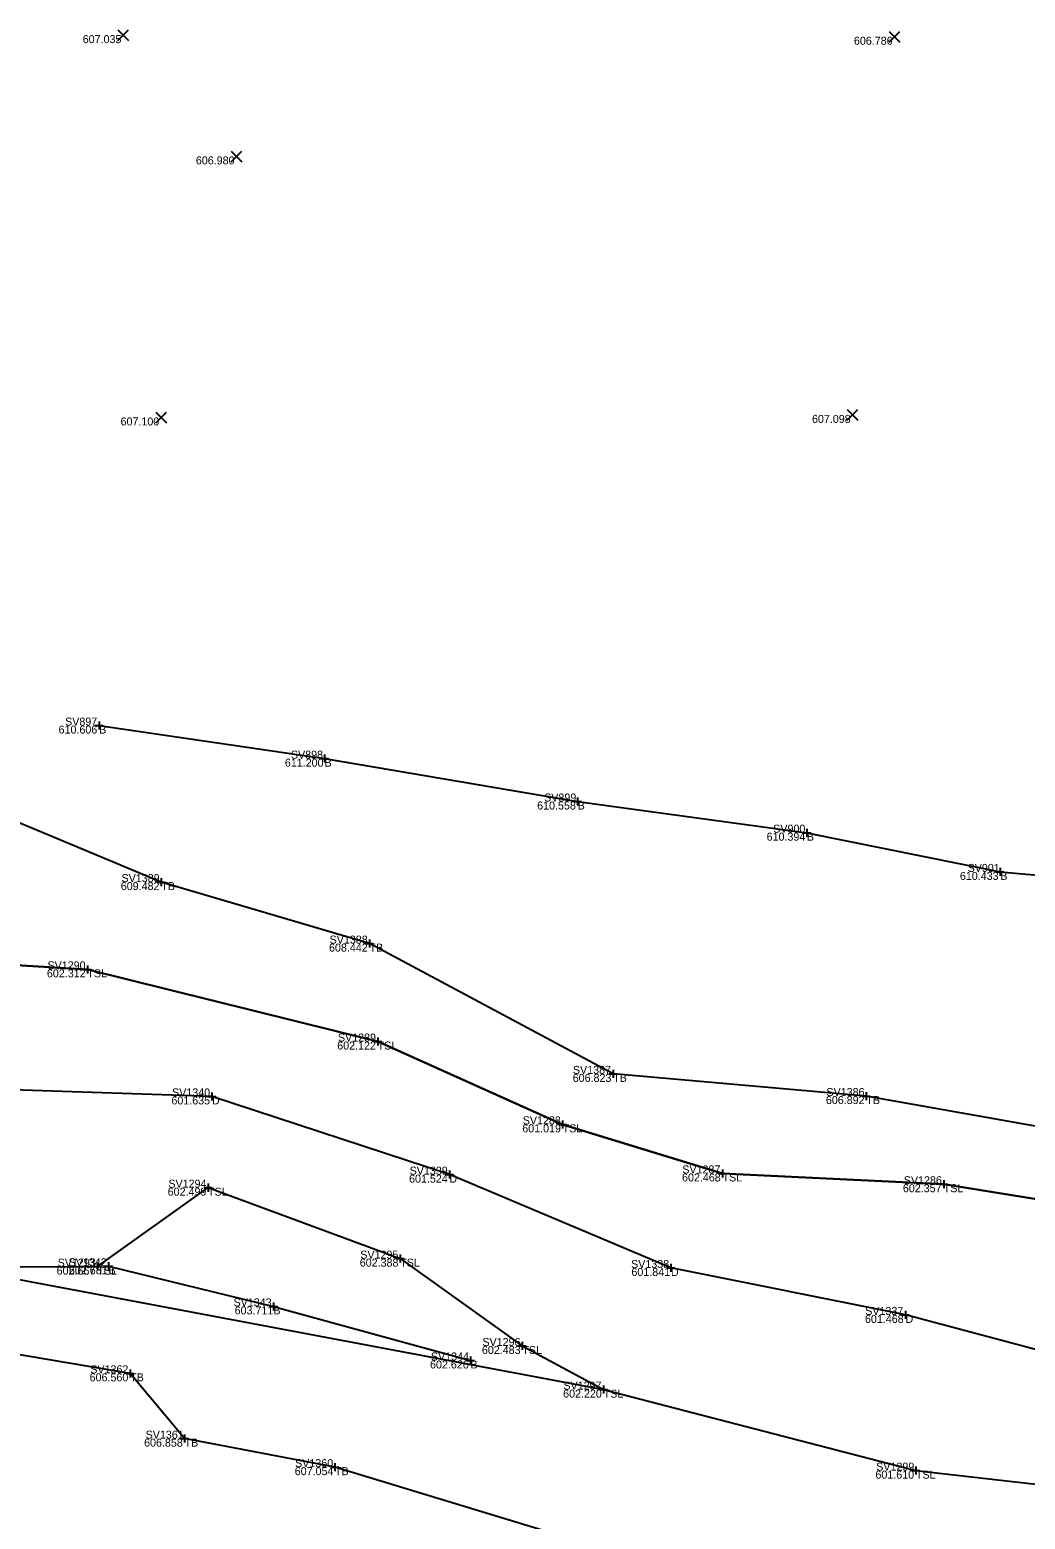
# Model space of a CAD drawing. Extents: x -2 to 1979875, y -2 to 232027.
# Drawn here: x 1978636.7 to 1978698.9, y 231261.4 to 231354.5 of the extents above; entities that cross this region are included whole.
import ezdxf

# ---------------------------------------------------------------- set-up
doc = ezdxf.new("R2010")
doc.units = 0
for name, color, linetype in [('_CIVIL_CONSTRUCTION', 7, 'Continuous'), ('DR_X_Ditch', 7, 'Continuous'), ('GE_P_Alignment', 7, 'Continuous'), ('GE_X_Alignment', 7, 'Continuous'), ('GE_X_Alignment_100_Curve_Data', 7, 'Continuous'), ('GE_X_Alignment_100_Stations', 7, 'Continuous'), ('HY_X_Water_Edge', 7, 'Continuous'), ('SV_X_Random_Point', 7, 'Continuous'), ('SV_X_Toe_of_Slope', 7, 'Continuous'), ('SV_X_Top_of_Bank', 7, 'Continuous')]:
    doc.layers.add(name, color=color, linetype=linetype)

msp = doc.modelspace()

# ---------------------------------------------------------------- linework, layer by layer
at = {"layer": 'DR_X_Ditch'}
msp.add_lwpolyline([(1978761.843, 231269.601), (1978754.066, 231268.151), (1978735.568, 231267.758), (1978719.025, 231269.165), (1978704.244, 231270.76), (1978691.436, 231274.176), (1978676.783, 231277.108), (1978662.935, 231282.94), (1978648.103, 231287.828), (1978629.385, 231288.446)], dxfattribs=at)
at = {"layer": 'GE_P_Alignment'}
for points in [[(1978641.051, 231310.998), (1978655.138, 231308.931), (1978670.953, 231306.253), (1978685.276, 231304.307), (1978697.362, 231301.855), (1978713.221, 231300.454), (1978725.92, 231300.85), (1978736.644, 231301.3), (1978747.238, 231303.286)], [(1978641.635, 231277.218), (1978651.938, 231274.71), (1978664.261, 231271.33)]]:
    msp.add_lwpolyline(points, dxfattribs=at)
at = {"layer": 'GE_X_Alignment_100_Curve_Data'}
for p, q in [((1978641.051, 231311.248), (1978641.051, 231310.748)), ((1978640.801, 231310.998), (1978641.301, 231310.998)), ((1978641.051, 231310.998), (1978641.051, 231310.998)), ((1978655.138, 231309.181), (1978655.138, 231308.681)), ((1978654.888, 231308.931), (1978655.388, 231308.931)), ((1978655.138, 231308.931), (1978655.138, 231308.931)), ((1978670.953, 231306.503), (1978670.953, 231306.003)), ((1978670.703, 231306.253), (1978671.203, 231306.253)), ((1978670.953, 231306.253), (1978670.953, 231306.253)), ((1978685.276, 231304.557), (1978685.276, 231304.057)), ((1978685.026, 231304.307), (1978685.526, 231304.307)), ((1978685.276, 231304.307), (1978685.276, 231304.307)), ((1978697.112, 231301.855), (1978697.612, 231301.855)), ((1978697.362, 231302.105), (1978697.362, 231301.605)), ((1978697.362, 231301.855), (1978697.362, 231301.855)), ((1978644.684, 231301.22), (1978645.184, 231301.22)), ((1978644.934, 231301.47), (1978644.934, 231300.97)), ((1978644.934, 231301.22), (1978644.934, 231301.22)), ((1978657.695, 231297.376), (1978658.195, 231297.376)), ((1978657.945, 231297.626), (1978657.945, 231297.126)), ((1978657.945, 231297.376), (1978657.945, 231297.376)), ((1978640.068, 231295.767), (1978640.568, 231295.767)), ((1978640.318, 231296.017), (1978640.318, 231295.517)), ((1978640.318, 231295.767), (1978640.318, 231295.767)), ((1978658.457, 231291.507), (1978658.457, 231291.007)), ((1978658.207, 231291.257), (1978658.707, 231291.257)), ((1978658.457, 231291.257), (1978658.457, 231291.257)), ((1978672.919, 231289.236), (1978673.419, 231289.236)), ((1978673.169, 231289.486), (1978673.169, 231288.986)), ((1978673.169, 231289.236), (1978673.169, 231289.236)), ((1978647.853, 231287.828), (1978648.353, 231287.828)), ((1978648.103, 231288.078), (1978648.103, 231287.578)), ((1978648.103, 231287.828), (1978648.103, 231287.828)), ((1978688.741, 231287.85), (1978689.241, 231287.85)), ((1978688.991, 231288.1), (1978688.991, 231287.6)), ((1978688.991, 231287.85), (1978688.991, 231287.85)), ((1978669.763, 231286.083), (1978670.263, 231286.083)), ((1978670.013, 231286.333), (1978670.013, 231285.833)), ((1978670.013, 231286.083), (1978670.013, 231286.083)), ((1978662.935, 231283.19), (1978662.935, 231282.69)), ((1978680.005, 231283.266), (1978680.005, 231282.766)), ((1978647.857, 231282.377), (1978647.857, 231281.877)), ((1978662.685, 231282.94), (1978663.185, 231282.94)), ((1978662.935, 231282.94), (1978662.935, 231282.94)), ((1978679.755, 231283.016), (1978680.255, 231283.016)), ((1978680.005, 231283.016), (1978680.005, 231283.016)), ((1978693.576, 231282.342), (1978694.076, 231282.342)), ((1978693.826, 231282.592), (1978693.826, 231282.092)), ((1978693.826, 231282.342), (1978693.826, 231282.342)), ((1978647.607, 231282.127), (1978648.107, 231282.127)), ((1978647.857, 231282.127), (1978647.857, 231282.127)), ((1978659.618, 231277.693), (1978660.118, 231277.693)), ((1978659.868, 231277.943), (1978659.868, 231277.443)), ((1978659.868, 231277.693), (1978659.868, 231277.693)), ((1978640.697, 231277.193), (1978641.197, 231277.193)), ((1978640.947, 231277.443), (1978640.947, 231276.943)), ((1978640.947, 231277.193), (1978640.947, 231277.193)), ((1978641.385, 231277.218), (1978641.885, 231277.218)), ((1978641.635, 231277.468), (1978641.635, 231276.968)), ((1978641.635, 231277.218), (1978641.635, 231277.218)), ((1978676.533, 231277.108), (1978677.033, 231277.108)), ((1978676.783, 231277.358), (1978676.783, 231276.858)), ((1978676.783, 231277.108), (1978676.783, 231277.108)), ((1978651.938, 231274.96), (1978651.938, 231274.46)), ((1978651.688, 231274.71), (1978652.188, 231274.71)), ((1978651.938, 231274.71), (1978651.938, 231274.71)), ((1978691.186, 231274.176), (1978691.686, 231274.176)), ((1978691.436, 231274.426), (1978691.436, 231273.926)), ((1978691.436, 231274.176), (1978691.436, 231274.176)), ((1978667.245, 231272.236), (1978667.745, 231272.236)), ((1978667.495, 231272.486), (1978667.495, 231271.986)), ((1978667.495, 231272.236), (1978667.495, 231272.236)), ((1978664.011, 231271.33), (1978664.511, 231271.33)), ((1978664.261, 231271.58), (1978664.261, 231271.08)), ((1978664.261, 231271.33), (1978664.261, 231271.33)), ((1978642.74, 231270.526), (1978643.24, 231270.526)), ((1978642.99, 231270.776), (1978642.99, 231270.276)), ((1978642.99, 231270.526), (1978642.99, 231270.526)), ((1978672.326, 231269.509), (1978672.826, 231269.509)), ((1978672.576, 231269.759), (1978672.576, 231269.259)), ((1978672.576, 231269.509), (1978672.576, 231269.509)), ((1978646.141, 231266.446), (1978646.641, 231266.446)), ((1978646.391, 231266.696), (1978646.391, 231266.196)), ((1978646.391, 231266.446), (1978646.391, 231266.446)), ((1978655.54, 231264.664), (1978656.04, 231264.664)), ((1978655.79, 231264.914), (1978655.79, 231264.414)), ((1978655.79, 231264.664), (1978655.79, 231264.664)), ((1978692.09, 231264.697), (1978692.09, 231264.197)), ((1978691.84, 231264.447), (1978692.34, 231264.447)), ((1978692.09, 231264.447), (1978692.09, 231264.447))]:
    msp.add_line(p, q, dxfattribs=at)
at = {"layer": 'HY_X_Water_Edge'}
for points in [[(1978627.995, 231296.512), (1978640.318, 231295.767), (1978658.457, 231291.257), (1978670.013, 231286.083), (1978680.005, 231283.016), (1978693.826, 231282.342), (1978711.084, 231279.554), (1978722.197, 231278.71), (1978738.528, 231278.008), (1978757.257, 231280.755)], [(1978631.824, 231277.19), (1978672.576, 231269.509), (1978692.09, 231264.447), (1978710.396, 231262.363), (1978725.371, 231260.246)]]:
    msp.add_lwpolyline(points, dxfattribs=at)
at = {"layer": 'SV_X_Random_Point'}
for p, q in [((1978642.228, 231353.803), (1978642.894, 231354.471)), ((1978642.228, 231354.471), (1978642.894, 231353.803)), ((1978690.415, 231353.702), (1978691.081, 231354.37)), ((1978690.415, 231354.37), (1978691.081, 231353.702)), ((1978649.294, 231346.226), (1978649.96, 231346.894)), ((1978649.294, 231346.894), (1978649.96, 231346.226)), ((1978644.59, 231329.916), (1978645.256, 231330.584)), ((1978644.59, 231330.584), (1978645.256, 231329.916)), ((1978687.793, 231330.075), (1978688.459, 231330.743)), ((1978687.793, 231330.743), (1978688.459, 231330.075))]:
    msp.add_line(p, q, dxfattribs=at)
at = {"layer": 'SV_X_Toe_of_Slope'}
for points in [[(1978763.371, 231281.556), (1978757.257, 231280.755), (1978753.761, 231278.898), (1978748.177, 231275.596), (1978738.528, 231278.008), (1978722.197, 231278.71), (1978711.084, 231279.554), (1978693.826, 231282.342), (1978680.005, 231283.016), (1978670.013, 231286.083), (1978658.457, 231291.257), (1978640.318, 231295.767), (1978627.995, 231296.512)], [(1978631.824, 231277.19), (1978640.947, 231277.193), (1978647.857, 231282.127), (1978659.868, 231277.693), (1978667.495, 231272.236), (1978672.576, 231269.509), (1978692.09, 231264.447), (1978710.396, 231262.363), (1978725.371, 231260.246), (1978739.363, 231256.715), (1978742.039, 231254.081), (1978741.875, 231245.466), (1978742.317, 231240.483), (1978743.738, 231236.887), (1978745.947, 231227.451)]]:
    msp.add_lwpolyline(points, dxfattribs=at)
at = {"layer": 'SV_X_Top_of_Bank'}
for points in [[(1978723.688, 231283.348), (1978710.826, 231283.978), (1978688.991, 231287.85), (1978673.169, 231289.236), (1978657.945, 231297.376), (1978644.934, 231301.22), (1978630.359, 231307.302)], [(1978743.6, 231227.215), (1978742.461, 231237.956), (1978739.46, 231251.574), (1978732.39, 231256.429), (1978722.837, 231257.109), (1978701.711, 231257.875), (1978681.567, 231257.575), (1978668.738, 231260.724), (1978655.79, 231264.664), (1978646.391, 231266.446), (1978642.99, 231270.526), (1978631.535, 231272.449)]]:
    msp.add_lwpolyline(points, dxfattribs=at)

# ---------------------------------------------------------------- texts
at = {"layer": '_CIVIL_CONSTRUCTION'}
for s, p in [('607.035', (1978640.026, 231353.637)), ('606.786', (1978688.216, 231353.536)), ('606.980', (1978647.097, 231346.06)), ('607.100', (1978642.393, 231329.75)), ('607.098', (1978685.596, 231329.909)), ('610.606', (1978638.519, 231310.498)), ('611.200', (1978652.659, 231308.431)), ('610.558', (1978668.423, 231305.753)), ('610.394', (1978682.76, 231303.807)), ('610.433', (1978694.837, 231301.355)), ('609.482', (1978642.406, 231300.72)), ('608.442', (1978655.417, 231296.876)), ('602.312', (1978637.79, 231295.267)), ('602.122', (1978655.929, 231290.757)), ('606.823', (1978670.644, 231288.736)), ('601.635', (1978645.568, 231287.328)), ('606.892', (1978686.463, 231287.35)), ('601.019', (1978667.492, 231285.583)), ('601.524', (1978660.419, 231282.44)), ('602.468', (1978677.475, 231282.516)), ('602.357', (1978691.275, 231281.842)), ('602.499', (1978645.336, 231281.627)), ('602.388', (1978657.338, 231277.193)), ('602.667', (1978638.396, 231276.693)), ('602.681', (1978639.165, 231276.718)), ('601.841', (1978674.313, 231276.608)), ('603.711', (1978649.52, 231274.21)), ('601.468', (1978688.906, 231273.676)), ('602.483', (1978664.97, 231271.736)), ('602.626', (1978661.729, 231270.83)), ('606.560', (1978640.46, 231270.026)), ('602.220', (1978670.046, 231269.009)), ('606.858', (1978643.861, 231265.946)), ('607.054', (1978653.274, 231264.164)), ('601.610', (1978689.56, 231263.947))]:
    msp.add_text(s, height=0.5, dxfattribs=at).set_placement(p)
at = {"layer": 'GE_X_Alignment'}
for s, p in [('SV897', (1978638.926, 231310.998)), ('SV898', (1978653.035, 231308.931)), ('SV899', (1978668.859, 231306.253)), ('SV900', (1978683.172, 231304.307)), ('SV901', (1978695.319, 231301.855)), ('SV1389', (1978642.452, 231301.22)), ('SV1388', (1978655.454, 231297.376)), ('SV1290', (1978637.826, 231295.767)), ('SV1289', (1978655.975, 231291.257)), ('SV1387', (1978670.656, 231289.236)), ('SV1340', (1978645.611, 231287.828)), ('SV1386', (1978686.497, 231287.85)), ('SV1288', (1978667.522, 231286.083)), ('SV1339', (1978660.453, 231282.94)), ('SV1287', (1978677.492, 231283.016)), ('SV1294', (1978645.38, 231282.127)), ('SV1286', (1978691.332, 231282.342)), ('SV1293', (1978638.461, 231277.193)), ('SV1342', (1978639.145, 231277.218)), ('SV1295', (1978657.371, 231277.693)), ('SV1338', (1978674.292, 231277.108)), ('SV1343', (1978649.452, 231274.71)), ('SV1337', (1978688.923, 231274.176)), ('SV1296', (1978665.001, 231272.236)), ('SV1362', (1978640.5, 231270.526)), ('SV1344', (1978661.784, 231271.33)), ('SV1297', (1978670.063, 231269.509)), ('SV1361', (1978643.959, 231266.446)), ('SV1360', (1978653.298, 231264.664)), ('SV1299', (1978689.608, 231264.447))]:
    msp.add_text(s, height=0.5, dxfattribs=at).set_placement(p)
at = {"layer": 'GE_X_Alignment_100_Stations'}
for s, p in [('B', (1978641.051, 231310.498)), ('B', (1978655.138, 231308.431)), ('B', (1978670.953, 231305.753)), ('B', (1978685.276, 231303.807)), ('B', (1978697.362, 231301.355)), ('TB', (1978644.934, 231300.72)), ('TB', (1978657.945, 231296.876)), ('TSL', (1978640.318, 231295.267)), ('TSL', (1978658.457, 231290.757)), ('TB', (1978673.169, 231288.736)), ('D', (1978648.103, 231287.328)), ('TB', (1978688.991, 231287.35)), ('TSL', (1978670.013, 231285.583)), ('D', (1978662.935, 231282.44)), ('TSL', (1978680.005, 231282.516)), ('TSL', (1978693.826, 231281.842)), ('TSL', (1978647.857, 231281.627)), ('TSL', (1978659.868, 231277.193)), ('TSL', (1978640.947, 231276.693)), ('B', (1978641.635, 231276.718)), ('D', (1978676.783, 231276.608)), ('B', (1978651.938, 231274.21)), ('D', (1978691.436, 231273.676)), ('TSL', (1978667.495, 231271.736)), ('B', (1978664.261, 231270.83)), ('TB', (1978642.99, 231270.026)), ('TSL', (1978672.576, 231269.009)), ('TB', (1978646.391, 231265.946)), ('TB', (1978655.79, 231264.164)), ('TSL', (1978692.09, 231263.947))]:
    msp.add_text(s, height=0.5, dxfattribs=at).set_placement(p)

doc.saveas('drawing.dxf')
